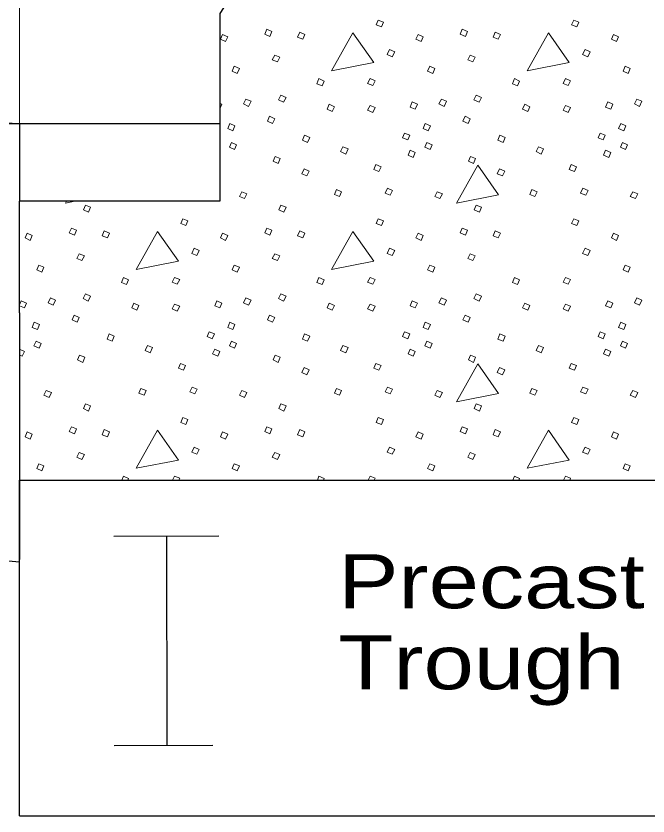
# Model space of a CAD drawing. Extents: x -1431.2 to -1397.2, y -1045.1 to -1001.1.
# Drawn here: x -1423.363 to -1421.507, y -1032.02 to -1029.669 of the extents above; entities that cross this region are included whole.
import ezdxf

# ---------------------------------------------------------------- set-up
doc = ezdxf.new("R2010")
doc.units = 0
doc.header["$LTSCALE"] = 0.064
doc.layers.add('1', color=7, linetype='Continuous', lineweight=13)

msp = doc.modelspace()

# ---------------------------------------------------------------- linework, layer by layer
at = {"layer": '1'}
for p, q in [((-1423.35233, -1029.98658), (-1423.35233, -1025.30175)), ((-1423.35233, -1029.98658), (-1423.39458, -1029.98658)), ((-1423.35233, -1030.51817), (-1423.34742, -1030.50592)), ((-1423.052, -1031.03292), (-1423.04733, -1031.02133)), ((-1422.90308, -1031.03292), (-1422.89733, -1031.02133)), ((-1422.47808, -1031.03292), (-1422.47342, -1031.02133)), ((-1422.32917, -1031.03292), (-1422.32342, -1031.02133)), ((-1421.90417, -1031.03292), (-1421.8995, -1031.02133)), ((-1421.75525, -1031.03292), (-1421.7495, -1031.02133))]:
    msp.add_line(p, q, dxfattribs=at)
at = {"layer": '1', "lineweight": 25}
for p, q in [((-1423.35233, -1029.98658), (-1424.476, -1029.93225)), ((-1422.764, -1029.98658), (-1423.35233, -1029.98658)), ((-1423.35233, -1029.98658), (-1423.35233, -1030.21375)), ((-1423.35233, -1030.54167), (-1423.35233, -1030.21375)), ((-1423.35233, -1030.54167), (-1423.35233, -1031.03292)), ((-1423.35233, -1030.54167), (-1423.35233, -1031.26667)), ((-1423.35233, -1032.01983), (-1423.35233, -1031.03292)), ((-1423.35233, -1031.03292), (-1420.59358, -1031.03292)), ((-1423.07583, -1031.19733), (-1422.76692, -1031.1965)), ((-1422.92142, -1031.19692), (-1422.91983, -1031.81183)), ((-1423.35233, -1031.27408), (-1423.729, -1031.24108)), ((-1423.07425, -1031.81225), (-1422.785, -1031.8115)), ((-1423.35233, -1032.01983), (-1420.59358, -1032.01983))]:
    msp.add_line(p, q, dxfattribs=at)
msp.add_lwpolyline([(-1421.842, -1026.66275), (-1422.06608, -1028.58492), (-1422.764, -1029.662), (-1422.764, -1030.21375), (-1423.35233, -1030.21375)], dxfattribs=at)
at = {"layer": '1'}
for points in [[(-1422.29925, -1029.68133), (-1422.28417, -1029.68742), (-1422.29017, -1029.7015), (-1422.30533, -1029.69542)], [(-1421.72533, -1029.68133), (-1421.71025, -1029.68742), (-1421.71625, -1029.7015), (-1421.73142, -1029.69542)], [(-1422.75642, -1029.72367), (-1422.74125, -1029.73067), (-1422.74733, -1029.74475), (-1422.76242, -1029.73775)], [(-1422.6265, -1029.70858), (-1422.61142, -1029.71458), (-1422.61742, -1029.72967), (-1422.6325, -1029.72267)], [(-1422.52983, -1029.71658), (-1422.51475, -1029.72367), (-1422.52075, -1029.73775), (-1422.53592, -1029.73167)], [(-1422.37375, -1029.71858), (-1422.43617, -1029.83033), (-1422.31233, -1029.80617)], [(-1422.1825, -1029.72367), (-1422.16733, -1029.73067), (-1422.17342, -1029.74475), (-1422.1885, -1029.73775)], [(-1422.05258, -1029.70858), (-1422.0375, -1029.71458), (-1422.0435, -1029.72967), (-1422.05858, -1029.72267)], [(-1421.95592, -1029.71658), (-1421.94083, -1029.72367), (-1421.94683, -1029.73775), (-1421.962, -1029.73167)], [(-1421.79983, -1029.71858), (-1421.86225, -1029.83033), (-1421.73842, -1029.80617)], [(-1421.60858, -1029.72367), (-1421.59342, -1029.73067), (-1421.5995, -1029.74475), (-1421.61458, -1029.73775)], [(-1422.266, -1029.76792), (-1422.25092, -1029.775), (-1422.258, -1029.78908), (-1422.27308, -1029.78308)], [(-1421.69208, -1029.76792), (-1421.677, -1029.775), (-1421.68408, -1029.78908), (-1421.69917, -1029.78308)], [(-1422.60333, -1029.78408), (-1422.58825, -1029.79008), (-1422.59525, -1029.80417), (-1422.61042, -1029.79817)], [(-1422.02942, -1029.78408), (-1422.01433, -1029.79008), (-1422.02133, -1029.80417), (-1422.0365, -1029.79817)], [(-1422.72217, -1029.81725), (-1422.70708, -1029.82333), (-1422.71308, -1029.83842), (-1422.72817, -1029.83133)], [(-1422.14825, -1029.81725), (-1422.13308, -1029.82333), (-1422.13917, -1029.83842), (-1422.15425, -1029.83133)], [(-1421.57433, -1029.81725), (-1421.55917, -1029.82333), (-1421.56525, -1029.83842), (-1421.58033, -1029.83133)], [(-1422.47342, -1029.8535), (-1422.45833, -1029.86058), (-1422.46442, -1029.87467), (-1422.4795, -1029.86858)], [(-1422.32342, -1029.8535), (-1422.30833, -1029.85958), (-1422.31533, -1029.87367), (-1422.3305, -1029.86758)], [(-1421.8995, -1029.8535), (-1421.88442, -1029.86058), (-1421.8905, -1029.87467), (-1421.90558, -1029.86858)], [(-1421.7495, -1029.8535), (-1421.73442, -1029.85958), (-1421.74142, -1029.87367), (-1421.75658, -1029.86758)], [(-1422.68792, -1029.91392), (-1422.67283, -1029.92), (-1422.67983, -1029.93508), (-1422.695, -1029.928)], [(-1422.58525, -1029.90183), (-1422.57008, -1029.90892), (-1422.57717, -1029.923), (-1422.59225, -1029.91592)], [(-1422.114, -1029.91392), (-1422.09892, -1029.92), (-1422.10592, -1029.93508), (-1422.12108, -1029.928)], [(-1422.01133, -1029.90183), (-1421.99617, -1029.90892), (-1422.00325, -1029.923), (-1422.01833, -1029.91592)], [(-1421.54008, -1029.91392), (-1421.525, -1029.92), (-1421.532, -1029.93508), (-1421.54708, -1029.928)], [(-1422.44325, -1029.929), (-1422.42817, -1029.93608), (-1422.43417, -1029.95017), (-1422.44925, -1029.94308)], [(-1422.32342, -1029.932), (-1422.30833, -1029.93808), (-1422.31533, -1029.95317), (-1422.3305, -1029.94617)], [(-1422.19958, -1029.922), (-1422.1845, -1029.929), (-1422.1905, -1029.94308), (-1422.20558, -1029.93708)], [(-1421.86933, -1029.929), (-1421.85425, -1029.93608), (-1421.86025, -1029.95017), (-1421.87533, -1029.94308)], [(-1421.7495, -1029.932), (-1421.73442, -1029.93808), (-1421.74142, -1029.95317), (-1421.75658, -1029.94617)], [(-1421.62567, -1029.922), (-1421.61058, -1029.929), (-1421.61658, -1029.94308), (-1421.63167, -1029.93708)], [(-1422.61842, -1029.96425), (-1422.60333, -1029.97133), (-1422.60942, -1029.98542), (-1422.6245, -1029.97833)], [(-1422.0445, -1029.96425), (-1422.02942, -1029.97133), (-1422.0355, -1029.98542), (-1422.05058, -1029.97833)], [(-1422.73525, -1029.98542), (-1422.72017, -1029.99242), (-1422.72617, -1030.00658), (-1422.74125, -1030.0005)], [(-1422.16133, -1029.98542), (-1422.14625, -1029.99242), (-1422.15225, -1030.00658), (-1422.16733, -1030.0005)], [(-1421.58742, -1029.98542), (-1421.57233, -1029.99242), (-1421.57833, -1030.00658), (-1421.59342, -1030.0005)], [(-1422.51575, -1030.01967), (-1422.50067, -1030.02667), (-1422.50667, -1030.04075), (-1422.52175, -1030.03475)], [(-1422.22175, -1030.01358), (-1422.20667, -1030.01967), (-1422.21267, -1030.03375), (-1422.22775, -1030.02767)], [(-1421.94183, -1030.01967), (-1421.92675, -1030.02667), (-1421.93275, -1030.04075), (-1421.94783, -1030.03475)], [(-1421.64783, -1030.01358), (-1421.63275, -1030.01967), (-1421.63875, -1030.03375), (-1421.65383, -1030.02767)], [(-1422.73017, -1030.04075), (-1422.71508, -1030.04783), (-1422.72117, -1030.06192), (-1422.73625, -1030.05483)], [(-1422.403, -1030.05383), (-1422.38783, -1030.05992), (-1422.39492, -1030.075), (-1422.41, -1030.06792)], [(-1422.15625, -1030.04075), (-1422.14117, -1030.04783), (-1422.14725, -1030.06192), (-1422.16233, -1030.05483)], [(-1421.82908, -1030.05383), (-1421.81392, -1030.05992), (-1421.821, -1030.075), (-1421.83608, -1030.06792)], [(-1421.58233, -1030.04075), (-1421.56725, -1030.04783), (-1421.57333, -1030.06192), (-1421.58842, -1030.05483)], [(-1422.20558, -1030.06392), (-1422.1905, -1030.071), (-1422.19658, -1030.08508), (-1422.21167, -1030.078)], [(-1421.63167, -1030.06392), (-1421.61658, -1030.071), (-1421.62267, -1030.08508), (-1421.63775, -1030.078)], [(-1422.60233, -1030.08208), (-1422.58725, -1030.08808), (-1422.59325, -1030.10317), (-1422.60833, -1030.09617)], [(-1422.02842, -1030.08208), (-1422.01333, -1030.08808), (-1422.01933, -1030.10317), (-1422.03442, -1030.09617)], [(-1422.51675, -1030.11825), (-1422.50167, -1030.12533), (-1422.50867, -1030.13942), (-1422.52383, -1030.13342)], [(-1422.30633, -1030.10625), (-1422.29117, -1030.11225), (-1422.29725, -1030.12633), (-1422.31233, -1030.12033)], [(-1422.00725, -1030.10725), (-1422.06967, -1030.219), (-1421.94583, -1030.19483)], [(-1421.94283, -1030.11825), (-1421.92775, -1030.12533), (-1421.93475, -1030.13942), (-1421.94992, -1030.13342)], [(-1421.73242, -1030.10625), (-1421.71725, -1030.11225), (-1421.72333, -1030.12633), (-1421.73842, -1030.12033)], [(-1422.7, -1030.18575), (-1422.68492, -1030.19175), (-1422.69192, -1030.20592), (-1422.70708, -1030.19983)], [(-1422.42208, -1030.17967), (-1422.407, -1030.18575), (-1422.413, -1030.19983), (-1422.42817, -1030.19383)], [(-1422.27208, -1030.17567), (-1422.257, -1030.18175), (-1422.264, -1030.19583), (-1422.27908, -1030.18975)], [(-1422.12608, -1030.18575), (-1422.111, -1030.19175), (-1422.118, -1030.20592), (-1422.13308, -1030.19983)], [(-1421.84817, -1030.17967), (-1421.83308, -1030.18575), (-1421.83908, -1030.19983), (-1421.85425, -1030.19383)], [(-1421.69817, -1030.17567), (-1421.68308, -1030.18175), (-1421.69008, -1030.19583), (-1421.70517, -1030.18975)], [(-1421.55217, -1030.18575), (-1421.53708, -1030.19175), (-1421.54408, -1030.20592), (-1421.55917, -1030.19983)], [(-1423.15908, -1030.225), (-1423.144, -1030.23108), (-1423.15008, -1030.24617), (-1423.16517, -1030.23908)], [(-1422.58525, -1030.225), (-1422.57008, -1030.23108), (-1422.57617, -1030.24617), (-1422.59125, -1030.23908)], [(-1422.01133, -1030.225), (-1421.99617, -1030.23108), (-1422.00225, -1030.24617), (-1422.01733, -1030.23908)], [(-1422.87317, -1030.26525), (-1422.85808, -1030.27133), (-1422.86408, -1030.28542), (-1422.87925, -1030.27933)], [(-1422.29925, -1030.26525), (-1422.28417, -1030.27133), (-1422.29017, -1030.28542), (-1422.30533, -1030.27933)], [(-1421.72533, -1030.26525), (-1421.71025, -1030.27133), (-1421.71625, -1030.28542), (-1421.73142, -1030.27933)], [(-1423.33033, -1030.30758), (-1423.31517, -1030.31458), (-1423.32125, -1030.32867), (-1423.33633, -1030.32167)], [(-1423.20042, -1030.2925), (-1423.18533, -1030.2985), (-1423.19133, -1030.31358), (-1423.20642, -1030.30658)], [(-1423.10375, -1030.3005), (-1423.08867, -1030.30758), (-1423.09467, -1030.32167), (-1423.10975, -1030.31558)], [(-1422.94767, -1030.3025), (-1423.01008, -1030.41425), (-1422.88625, -1030.39008)], [(-1422.75642, -1030.30758), (-1422.74125, -1030.31458), (-1422.74733, -1030.32867), (-1422.76242, -1030.32167)], [(-1422.6265, -1030.2925), (-1422.61142, -1030.2985), (-1422.61742, -1030.31358), (-1422.6325, -1030.30658)], [(-1422.52983, -1030.3005), (-1422.51475, -1030.30758), (-1422.52075, -1030.32167), (-1422.53592, -1030.31558)], [(-1422.37375, -1030.3025), (-1422.43617, -1030.41425), (-1422.31233, -1030.39008)], [(-1422.1825, -1030.30758), (-1422.16733, -1030.31458), (-1422.17342, -1030.32867), (-1422.1885, -1030.32167)], [(-1422.05258, -1030.2925), (-1422.0375, -1030.2985), (-1422.0435, -1030.31358), (-1422.05858, -1030.30658)], [(-1421.95592, -1030.3005), (-1421.94083, -1030.30758), (-1421.94683, -1030.32167), (-1421.962, -1030.31558)], [(-1421.60858, -1030.30758), (-1421.59342, -1030.31458), (-1421.5995, -1030.32867), (-1421.61458, -1030.32167)], [(-1422.83992, -1030.35183), (-1422.82483, -1030.35892), (-1422.83192, -1030.373), (-1422.847, -1030.367)], [(-1422.266, -1030.35183), (-1422.25092, -1030.35892), (-1422.258, -1030.373), (-1422.27308, -1030.367)], [(-1421.69208, -1030.35183), (-1421.677, -1030.35892), (-1421.68408, -1030.373), (-1421.69917, -1030.367)], [(-1423.17725, -1030.368), (-1423.16217, -1030.374), (-1423.16917, -1030.38808), (-1423.18433, -1030.38208)], [(-1422.60333, -1030.368), (-1422.58825, -1030.374), (-1422.59525, -1030.38808), (-1422.61042, -1030.38208)], [(-1422.02942, -1030.368), (-1422.01433, -1030.374), (-1422.02133, -1030.38808), (-1422.0365, -1030.38208)], [(-1423.29608, -1030.40117), (-1423.28092, -1030.40725), (-1423.287, -1030.42233), (-1423.30208, -1030.41525)], [(-1422.72217, -1030.40117), (-1422.70708, -1030.40725), (-1422.71308, -1030.42233), (-1422.72817, -1030.41525)], [(-1422.14825, -1030.40117), (-1422.13308, -1030.40725), (-1422.13917, -1030.42233), (-1422.15425, -1030.41525)], [(-1421.57433, -1030.40117), (-1421.55917, -1030.40725), (-1421.56525, -1030.42233), (-1421.58033, -1030.41525)], [(-1423.04733, -1030.43742), (-1423.03225, -1030.4445), (-1423.03833, -1030.45858), (-1423.05342, -1030.4525)], [(-1422.89733, -1030.43742), (-1422.88225, -1030.4435), (-1422.88925, -1030.45758), (-1422.90442, -1030.4515)], [(-1422.47342, -1030.43742), (-1422.45833, -1030.4445), (-1422.46442, -1030.45858), (-1422.4795, -1030.4525)], [(-1422.32342, -1030.43742), (-1422.30833, -1030.4435), (-1422.31533, -1030.45758), (-1422.3305, -1030.4515)], [(-1421.8995, -1030.43742), (-1421.88442, -1030.4445), (-1421.8905, -1030.45858), (-1421.90558, -1030.4525)], [(-1421.7495, -1030.43742), (-1421.73442, -1030.4435), (-1421.74142, -1030.45758), (-1421.75658, -1030.4515)], [(-1423.26183, -1030.49783), (-1423.24675, -1030.50392), (-1423.25375, -1030.519), (-1423.26883, -1030.51192)], [(-1423.15908, -1030.48575), (-1423.144, -1030.49283), (-1423.15108, -1030.50692), (-1423.16617, -1030.49983)], [(-1422.68792, -1030.49783), (-1422.67283, -1030.50392), (-1422.67983, -1030.519), (-1422.695, -1030.51192)], [(-1422.58525, -1030.48575), (-1422.57008, -1030.49283), (-1422.57717, -1030.50692), (-1422.59225, -1030.49983)], [(-1422.114, -1030.49783), (-1422.09892, -1030.50392), (-1422.10592, -1030.519), (-1422.12108, -1030.51192)], [(-1422.01133, -1030.48575), (-1421.99617, -1030.49283), (-1422.00325, -1030.50692), (-1422.01833, -1030.49983)], [(-1421.54008, -1030.49783), (-1421.525, -1030.50392), (-1421.532, -1030.519), (-1421.54708, -1030.51192)], [(-1423.01717, -1030.51292), (-1423.00208, -1030.52), (-1423.00808, -1030.53408), (-1423.02317, -1030.527)], [(-1422.89733, -1030.516), (-1422.88225, -1030.522), (-1422.88925, -1030.53708), (-1422.90442, -1030.53008)], [(-1422.7735, -1030.50592), (-1422.75842, -1030.51292), (-1422.76442, -1030.527), (-1422.7795, -1030.521)], [(-1422.44325, -1030.51292), (-1422.42817, -1030.52), (-1422.43417, -1030.53408), (-1422.44925, -1030.527)], [(-1422.32342, -1030.516), (-1422.30833, -1030.522), (-1422.31533, -1030.53708), (-1422.3305, -1030.53008)], [(-1422.19958, -1030.50592), (-1422.1845, -1030.51292), (-1422.1905, -1030.527), (-1422.20558, -1030.521)], [(-1421.86933, -1030.51292), (-1421.85425, -1030.52), (-1421.86025, -1030.53408), (-1421.87533, -1030.527)], [(-1421.7495, -1030.516), (-1421.73442, -1030.522), (-1421.74142, -1030.53708), (-1421.75658, -1030.53008)], [(-1421.62567, -1030.50592), (-1421.61058, -1030.51292), (-1421.61658, -1030.527), (-1421.63167, -1030.521)], [(-1423.19233, -1030.54817), (-1423.17725, -1030.55525), (-1423.18325, -1030.56933), (-1423.19842, -1030.56225)], [(-1422.61842, -1030.54817), (-1422.60333, -1030.55525), (-1422.60942, -1030.56933), (-1422.6245, -1030.56225)], [(-1422.0445, -1030.54817), (-1422.02942, -1030.55525), (-1422.0355, -1030.56933), (-1422.05058, -1030.56225)], [(-1423.30917, -1030.56933), (-1423.29408, -1030.57633), (-1423.30008, -1030.5905), (-1423.31517, -1030.58442)], [(-1422.73525, -1030.56933), (-1422.72017, -1030.57633), (-1422.72617, -1030.5905), (-1422.74125, -1030.58442)], [(-1422.16133, -1030.56933), (-1422.14625, -1030.57633), (-1422.15225, -1030.5905), (-1422.16733, -1030.58442)], [(-1421.58742, -1030.56933), (-1421.57233, -1030.57633), (-1421.57833, -1030.5905), (-1421.59342, -1030.58442)], [(-1423.08967, -1030.60358), (-1423.07458, -1030.61058), (-1423.08058, -1030.62467), (-1423.09567, -1030.61867)], [(-1422.79567, -1030.5975), (-1422.78058, -1030.60358), (-1422.78658, -1030.61767), (-1422.80167, -1030.61158)], [(-1422.51575, -1030.60358), (-1422.50067, -1030.61058), (-1422.50667, -1030.62467), (-1422.52175, -1030.61867)], [(-1422.22175, -1030.5975), (-1422.20667, -1030.60358), (-1422.21267, -1030.61767), (-1422.22775, -1030.61158)], [(-1421.94183, -1030.60358), (-1421.92675, -1030.61058), (-1421.93275, -1030.62467), (-1421.94783, -1030.61867)], [(-1421.64783, -1030.5975), (-1421.63275, -1030.60358), (-1421.63875, -1030.61767), (-1421.65383, -1030.61158)], [(-1423.30408, -1030.62467), (-1423.289, -1030.63175), (-1423.29508, -1030.64583), (-1423.31017, -1030.63883)], [(-1422.97692, -1030.63775), (-1422.96175, -1030.64383), (-1422.96883, -1030.65892), (-1422.98392, -1030.65183)], [(-1422.73017, -1030.62467), (-1422.71508, -1030.63175), (-1422.72117, -1030.64583), (-1422.73625, -1030.63883)], [(-1422.403, -1030.63775), (-1422.38783, -1030.64383), (-1422.39492, -1030.65892), (-1422.41, -1030.65183)], [(-1422.15625, -1030.62467), (-1422.14117, -1030.63175), (-1422.14725, -1030.64583), (-1422.16233, -1030.63883)], [(-1421.82908, -1030.63775), (-1421.81392, -1030.64383), (-1421.821, -1030.65892), (-1421.83608, -1030.65183)], [(-1421.58233, -1030.62467), (-1421.56725, -1030.63175), (-1421.57333, -1030.64583), (-1421.58842, -1030.63883)], [(-1423.17625, -1030.666), (-1423.16117, -1030.672), (-1423.16717, -1030.68708), (-1423.18225, -1030.68008)], [(-1422.7795, -1030.64783), (-1422.76442, -1030.65492), (-1422.7705, -1030.669), (-1422.78558, -1030.66192)], [(-1422.60233, -1030.666), (-1422.58725, -1030.672), (-1422.59325, -1030.68708), (-1422.60833, -1030.68008)], [(-1422.20558, -1030.64783), (-1422.1905, -1030.65492), (-1422.19658, -1030.669), (-1422.21167, -1030.66192)], [(-1422.02842, -1030.666), (-1422.01333, -1030.672), (-1422.01933, -1030.68708), (-1422.03442, -1030.68008)], [(-1421.63167, -1030.64783), (-1421.61658, -1030.65492), (-1421.62267, -1030.669), (-1421.63775, -1030.66192)], [(-1422.88025, -1030.69017), (-1422.86508, -1030.69617), (-1422.87117, -1030.71025), (-1422.88625, -1030.70425)], [(-1422.30633, -1030.69017), (-1422.29117, -1030.69617), (-1422.29725, -1030.71025), (-1422.31233, -1030.70425)], [(-1421.73242, -1030.69017), (-1421.71725, -1030.69617), (-1421.72333, -1030.71025), (-1421.73842, -1030.70425)], [(-1422.51675, -1030.70225), (-1422.50167, -1030.70925), (-1422.50867, -1030.72333), (-1422.52383, -1030.71733)], [(-1422.00725, -1030.69117), (-1422.06967, -1030.80292), (-1421.94583, -1030.77875)], [(-1421.94283, -1030.70225), (-1421.92775, -1030.70925), (-1421.93475, -1030.72333), (-1421.94992, -1030.71733)], [(-1422.846, -1030.75958), (-1422.83092, -1030.76567), (-1422.83792, -1030.77975), (-1422.853, -1030.77367)], [(-1422.27208, -1030.75958), (-1422.257, -1030.76567), (-1422.264, -1030.77975), (-1422.27908, -1030.77367)], [(-1421.69817, -1030.75958), (-1421.68308, -1030.76567), (-1421.69008, -1030.77975), (-1421.70517, -1030.77367)], [(-1423.27392, -1030.76967), (-1423.25883, -1030.77567), (-1423.26583, -1030.78983), (-1423.28092, -1030.78375)], [(-1422.996, -1030.76367), (-1422.98092, -1030.76967), (-1422.98692, -1030.78375), (-1423.00208, -1030.77775)], [(-1422.7, -1030.76967), (-1422.68492, -1030.77567), (-1422.69192, -1030.78983), (-1422.70708, -1030.78375)], [(-1422.42208, -1030.76367), (-1422.407, -1030.76967), (-1422.413, -1030.78375), (-1422.42817, -1030.77775)], [(-1422.12608, -1030.76967), (-1422.111, -1030.77567), (-1422.118, -1030.78983), (-1422.13308, -1030.78375)], [(-1421.84817, -1030.76367), (-1421.83308, -1030.76967), (-1421.83908, -1030.78375), (-1421.85425, -1030.77775)], [(-1421.55217, -1030.76967), (-1421.53708, -1030.77567), (-1421.54408, -1030.78983), (-1421.55917, -1030.78375)], [(-1423.15908, -1030.80892), (-1423.144, -1030.815), (-1423.15008, -1030.83008), (-1423.16517, -1030.823)], [(-1422.58525, -1030.80892), (-1422.57008, -1030.815), (-1422.57617, -1030.83008), (-1422.59125, -1030.823)], [(-1422.01133, -1030.80892), (-1421.99617, -1030.815), (-1422.00225, -1030.83008), (-1422.01733, -1030.823)], [(-1422.87317, -1030.84917), (-1422.85808, -1030.85525), (-1422.86408, -1030.86933), (-1422.87925, -1030.86333)], [(-1422.29925, -1030.84917), (-1422.28417, -1030.85525), (-1422.29017, -1030.86933), (-1422.30533, -1030.86333)], [(-1421.72533, -1030.84917), (-1421.71025, -1030.85525), (-1421.71625, -1030.86933), (-1421.73142, -1030.86333)], [(-1423.20042, -1030.87642), (-1423.18533, -1030.88242), (-1423.19133, -1030.8975), (-1423.20642, -1030.8905)], [(-1422.6265, -1030.87642), (-1422.61142, -1030.88242), (-1422.61742, -1030.8975), (-1422.6325, -1030.8905)], [(-1422.05258, -1030.87642), (-1422.0375, -1030.88242), (-1422.0435, -1030.8975), (-1422.05858, -1030.8905)], [(-1423.33033, -1030.8915), (-1423.31517, -1030.8985), (-1423.32125, -1030.91267), (-1423.33633, -1030.90558)], [(-1423.10375, -1030.88442), (-1423.08867, -1030.8915), (-1423.09467, -1030.90558), (-1423.10975, -1030.89958)], [(-1422.94767, -1030.88642), (-1423.01008, -1030.99817), (-1422.88625, -1030.97408)], [(-1422.75642, -1030.8915), (-1422.74125, -1030.8985), (-1422.74733, -1030.91267), (-1422.76242, -1030.90558)], [(-1422.52983, -1030.88442), (-1422.51475, -1030.8915), (-1422.52075, -1030.90558), (-1422.53592, -1030.89958)], [(-1422.1825, -1030.8915), (-1422.16733, -1030.8985), (-1422.17342, -1030.91267), (-1422.1885, -1030.90558)], [(-1421.95592, -1030.88442), (-1421.94083, -1030.8915), (-1421.94683, -1030.90558), (-1421.962, -1030.89958)], [(-1421.79983, -1030.88642), (-1421.86225, -1030.99817), (-1421.73842, -1030.97408)], [(-1421.60858, -1030.8915), (-1421.59342, -1030.8985), (-1421.5995, -1030.91267), (-1421.61458, -1030.90558)], [(-1422.83992, -1030.93575), (-1422.82483, -1030.94283), (-1422.83192, -1030.95692), (-1422.847, -1030.95092)], [(-1422.266, -1030.93575), (-1422.25092, -1030.94283), (-1422.258, -1030.95692), (-1422.27308, -1030.95092)], [(-1421.69208, -1030.93575), (-1421.677, -1030.94283), (-1421.68408, -1030.95692), (-1421.69917, -1030.95092)], [(-1423.17725, -1030.95192), (-1423.16217, -1030.95792), (-1423.16917, -1030.972), (-1423.18433, -1030.966)], [(-1422.60333, -1030.95192), (-1422.58825, -1030.95792), (-1422.59525, -1030.972), (-1422.61042, -1030.966)], [(-1422.02942, -1030.95192), (-1422.01433, -1030.95792), (-1422.02133, -1030.972), (-1422.0365, -1030.966)], [(-1423.29608, -1030.98508), (-1423.28092, -1030.99117), (-1423.287, -1031.00625), (-1423.30208, -1030.99925)], [(-1422.72217, -1030.98508), (-1422.70708, -1030.99117), (-1422.71308, -1031.00625), (-1422.72817, -1030.99925)], [(-1422.14825, -1030.98508), (-1422.13308, -1030.99117), (-1422.13917, -1031.00625), (-1422.15425, -1030.99925)], [(-1421.57433, -1030.98508), (-1421.55917, -1030.99117), (-1421.56525, -1031.00625), (-1421.58033, -1030.99925)]]:
    msp.add_lwpolyline(points, close=True, dxfattribs=at)
for points in [[(-1422.764, -1029.92642), (-1422.75842, -1029.929), (-1422.764, -1029.94217)], [(-1423.21458, -1030.21375), (-1423.2175, -1030.219), (-1423.19067, -1030.21375)], [(-1423.34742, -1030.50592), (-1423.33233, -1030.51292), (-1423.33833, -1030.527), (-1423.35233, -1030.52142)], [(-1423.35233, -1030.64833), (-1423.33833, -1030.65492), (-1423.34442, -1030.669), (-1423.35233, -1030.66525)], [(-1423.04733, -1031.02133), (-1423.03225, -1031.02842), (-1423.03417, -1031.03292)], [(-1422.89733, -1031.02133), (-1422.88225, -1031.02742), (-1422.88492, -1031.03292)], [(-1422.47342, -1031.02133), (-1422.45833, -1031.02842), (-1422.46025, -1031.03292)], [(-1422.32342, -1031.02133), (-1422.30833, -1031.02742), (-1422.31108, -1031.03292)], [(-1421.8995, -1031.02133), (-1421.88442, -1031.02842), (-1421.88633, -1031.03292)], [(-1421.7495, -1031.02133), (-1421.73442, -1031.02742), (-1421.73708, -1031.03292)]]:
    msp.add_lwpolyline(points, dxfattribs=at)

# ---------------------------------------------------------------- texts
at = {"layer": '1', "width": 1.25}
for s, p in [('Precast', (-1422.41675, -1031.40942)), ('Trough', (-1422.41675, -1031.64758))]:
    msp.add_text(s, height=0.1588, dxfattribs=at).set_placement(p)

doc.saveas('drawing.dxf')
